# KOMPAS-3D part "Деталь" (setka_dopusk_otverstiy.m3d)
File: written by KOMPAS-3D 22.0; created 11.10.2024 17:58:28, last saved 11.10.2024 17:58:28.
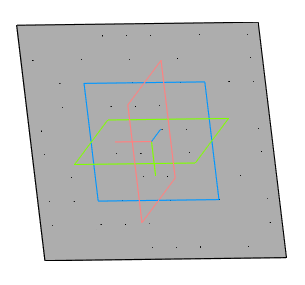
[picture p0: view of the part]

Document properties: Автор: zamut89@bk.ru; Полное имя файла: C:\Users\zamut\OneDrive\Desktop\сетка допуск отверстий .m3d

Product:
- Part/product: Деталь
    Масса: 0.007856

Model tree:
1. Эскиз:1
2. Элемент выдавливания:1
     Расстояние 1 = 0.1
3. Эскиз:2  (with: Элемент выдавливания:1)
4. Элемент выдавливания:2
     Расстояние 2 = 10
